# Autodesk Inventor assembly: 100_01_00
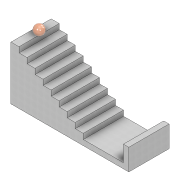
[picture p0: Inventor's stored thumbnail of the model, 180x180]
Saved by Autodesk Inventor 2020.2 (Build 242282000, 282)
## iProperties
Manager: www.cadconsulting.pl
Company: Fabian Stasiak CAD Consulting
Created: 2020-03
Part Number: 100_01_00
Document SubType Name: Assembly
Designer: F.Stasiak
Catalog Web Link: www.expertbooks.pl
Author: F.Stasiak
Subject: Zbiór ćwiczeń. Autodesk Inventor 2020. Kurs Professional
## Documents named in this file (3)
- C:\2020_Kurs_Professional\R3 Dynamika\100_01_00.iam
- C:\2020_Kurs_Professional\R3 Dynamika\Komponenty_dyn\100_01_Schody.ipt
- C:\2020_Kurs_Professional\R3 Dynamika\Komponenty_dyn\100_01_Kula.ipt
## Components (2 placed, 2 different names)
1. 100_01_Schody:1 — Zestawiające:1, Zestawiające:2, Zestawiające:3
2. 100_01_Kula:1 — Zestawiające:1, Zestawiające:2, Zestawiające:3
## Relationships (3: Mate 3)
- Zestawiające:1 [Mate]: 100_01_Schody:1 ↔ 100_01_Kula:1
- Zestawiające:2 [Mate]: 100_01_Schody:1 ↔ 100_01_Kula:1
- Zestawiające:3 [Mate]: 100_01_Schody:1 ↔ 100_01_Kula:1
